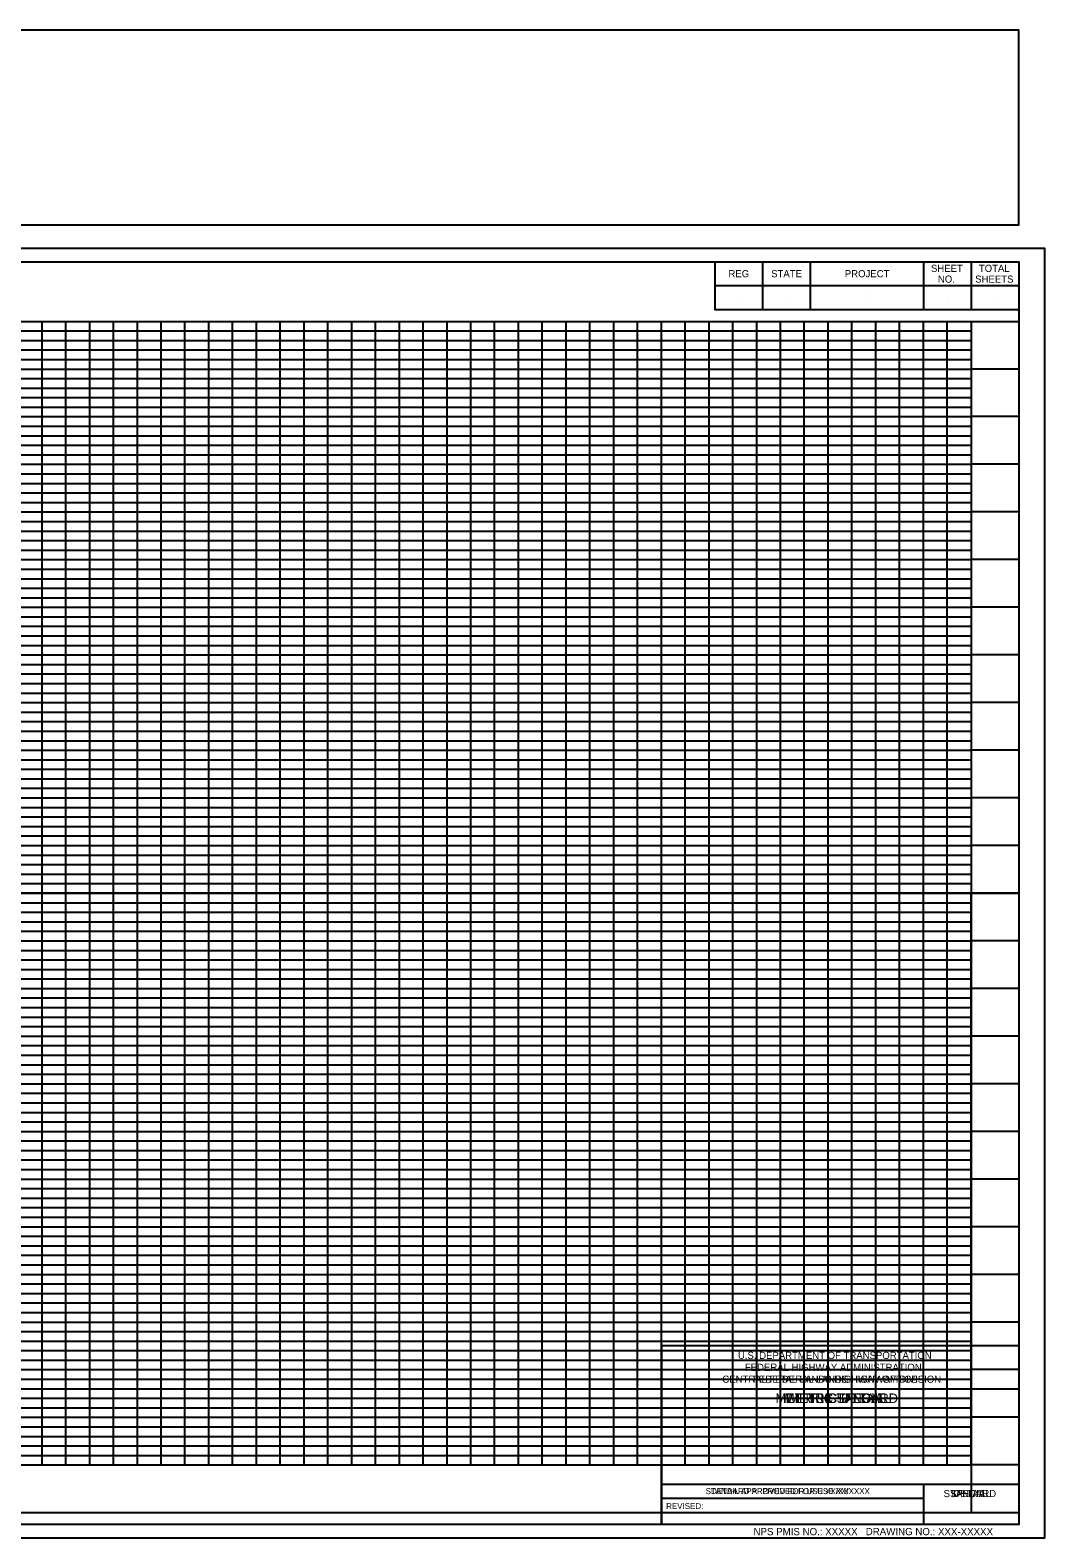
# Model space of a CAD drawing. Extents: x -27 to 395, y -3 to 314.
# Drawn here: x 182.5 to 395.5, y -2.8 to 313.6 of the extents above; entities that cross this region are included whole.
import ezdxf

# ---------------------------------------------------------------- set-up
doc = ezdxf.new("R2010")
doc.units = 0
for name, color, linetype in [('D_CFL_Clip_Boundary_1', 7, 'Continuous'), ('D_CFL_Clip_Boundary_2', 7, 'Continuous'), ('D_CFL_Sheet_Border_ PlotShape', 7, 'Continuous'), ('D_CFL_Sheet_Border_Base', 7, 'Continuous'), ('D_CFL_Sheet_Border_Box', 7, 'Continuous'), ('D_CFL_Sheet_Border_Detail', 7, 'Continuous'), ('D_CFL_Sheet_Border_General', 7, 'Continuous'), ('D_CFL_Sheet_Border_NPS_Pkg', 7, 'Continuous'), ('D_CFL_Sheet_Border_Plan_Plan', 7, 'Continuous'), ('D_CFL_Sheet_Border_PnP', 7, 'Continuous'), ('D_CFL_Sheet_Border_Profile', 7, 'Continuous'), ('D_CFL_Sheet_Border_Project_Info', 7, 'Continuous'), ('D_CFL_Sheet_Border_Special', 7, 'Continuous'), ('D_CFL_Sheet_Border_Standard', 7, 'Continuous')]:
    doc.layers.add(name, color=color, linetype=linetype)

msp = doc.modelspace()

# ---------------------------------------------------------------- linework, layer by layer
at = {"layer": 'D_CFL_Clip_Boundary_1'}
msp.add_lwpolyline([(0, 265), (326.25, 265), (326.25, 255), (390, 255), (390, 132.5), (0, 132.5)], close=True, dxfattribs=at)
at = {"layer": 'D_CFL_Clip_Boundary_2'}
msp.add_lwpolyline([(380, 132.5), (10, 132.5), (10, 12.5), (380, 12.5)], close=True, dxfattribs=at)
at = {"layer": 'D_CFL_Sheet_Border_ PlotShape'}
msp.add_line((395.49, 267.8), (395.49, 267.8), dxfattribs=at)
msp.add_lwpolyline([(-27.13, -2.8), (395.49, -2.8), (395.49, 267.8), (-27.13, 267.8)], close=True, dxfattribs=at)
at = {"layer": 'D_CFL_Sheet_Border_Base'}
for p, q in [((336.25, 265), (336.25, 255)), ((346.25, 265), (346.25, 255)), ((370, 265), (370, 255)), ((380, 265), (380, 255)), ((326.25, 260), (390, 260))]:
    msp.add_line(p, q, dxfattribs=at)
for points in [[(79.54, 272.77), (390, 272.77), (390, 313.62), (79.54, 313.62)], [(0, 265), (390, 265), (390, 0), (0, 0)]]:
    msp.add_lwpolyline(points, close=True, dxfattribs=at)
msp.add_lwpolyline([(326.25, 265), (326.25, 255), (390, 255)], dxfattribs=at)
at = {"layer": 'D_CFL_Sheet_Border_Box'}
for p, q in [((315, 0), (315, 28.5)), ((315, 28.5), (390, 28.5)), ((352.5, 17.25), (352.5, 17.25))]:
    msp.add_line(p, q, dxfattribs=at)
at = {"layer": 'D_CFL_Sheet_Border_Detail'}
for p, q in [((315, 28.5), (390, 28.5)), ((352.5, 17.25), (352.5, 17.25)), ((315, 8.5), (390, 8.5)), ((370, 8.5), (370, 0)), ((315, 5.5), (370, 5.5))]:
    msp.add_line(p, q, dxfattribs=at)
msp.add_lwpolyline([(390, 37.5), (315, 37.5), (315, 0)], dxfattribs=at)
at = {"layer": 'D_CFL_Sheet_Border_General'}
for p, q in [((315, 28.5), (390, 28.5)), ((352.5, 17.25), (352.5, 17.25))]:
    msp.add_line(p, q, dxfattribs=at)
msp.add_lwpolyline([(390, 37.5), (315, 37.5), (315, 0)], dxfattribs=at)
at = {"layer": 'D_CFL_Sheet_Border_Plan_Plan'}
for p, q in [((0, 132.5), (390, 132.5)), ((315, 0), (315, 28.5)), ((315, 28.5), (390, 28.5)), ((352.5, 17.25), (352.5, 17.25))]:
    msp.add_line(p, q, dxfattribs=at)
at = {"layer": 'D_CFL_Sheet_Border_PnP'}
for p, q in [((0, 132.5), (390, 132.5)), ((10, 130.5), (380, 130.5)), ((185, 12.5), (185, 132.5)), ((190, 12.5), (190, 132.5)), ((195, 12.5), (195, 132.5)), ((200, 12.5), (200, 132.5)), ((205, 12.5), (205, 132.5)), ((210, 12.5), (210, 132.5)), ((215, 12.5), (215, 132.5)), ((220, 12.5), (220, 132.5)), ((225, 12.5), (225, 132.5)), ((230, 12.5), (230, 132.5)), ((235, 12.5), (235, 132.5)), ((240, 12.5), (240, 132.5)), ((245, 12.5), (245, 132.5)), ((250, 12.5), (250, 132.5)), ((255, 12.5), (255, 132.5)), ((260, 12.5), (260, 132.5)), ((265, 12.5), (265, 132.5)), ((270, 12.5), (270, 132.5)), ((275, 12.5), (275, 132.5)), ((280, 12.5), (280, 132.5)), ((285, 12.5), (285, 132.5)), ((290, 12.5), (290, 132.5)), ((295, 12.5), (295, 132.5)), ((300, 12.5), (300, 132.5)), ((305, 12.5), (305, 132.5)), ((310, 12.5), (310, 132.5)), ((315, 12.5), (315, 132.5)), ((320, 12.5), (320, 132.5)), ((325, 12.5), (325, 132.5)), ((330, 12.5), (330, 132.5)), ((335, 12.5), (335, 132.5)), ((340, 12.5), (340, 132.5)), ((345, 12.5), (345, 132.5)), ((350, 12.5), (350, 132.5)), ((355, 12.5), (355, 132.5)), ((360, 12.5), (360, 132.5)), ((365, 12.5), (365, 132.5)), ((370, 12.5), (370, 132.5)), ((375, 12.5), (375, 132.5)), ((380, 132.5), (380, 2.5)), ((10, 128.5), (380, 128.5)), ((10, 126.5), (380, 126.5)), ((10, 124.5), (380, 124.5)), ((10, 122.5), (380, 122.5)), ((10, 120.5), (380, 120.5)), ((390, 122.5), (380, 122.5)), ((10, 118.5), (380, 118.5)), ((10, 116.5), (380, 116.5)), ((10, 114.5), (380, 114.5)), ((10, 112.5), (380, 112.5)), ((390, 112.5), (380, 112.5)), ((10, 110.5), (380, 110.5)), ((10, 108.5), (380, 108.5)), ((10, 106.5), (380, 106.5)), ((10, 104.5), (380, 104.5)), ((10, 102.5), (380, 102.5)), ((390, 102.5), (380, 102.5)), ((10, 100.5), (380, 100.5)), ((10, 98.5), (380, 98.5)), ((10, 96.5), (380, 96.5)), ((10, 94.5), (380, 94.5)), ((10, 92.5), (380, 92.5)), ((390, 92.5), (380, 92.5)), ((10, 90.5), (380, 90.5)), ((10, 88.5), (380, 88.5)), ((10, 86.5), (380, 86.5)), ((10, 84.5), (380, 84.5)), ((10, 82.5), (380, 82.5)), ((390, 82.5), (380, 82.5)), ((10, 80.5), (380, 80.5)), ((10, 78.5), (380, 78.5)), ((10, 76.5), (380, 76.5)), ((10, 74.5), (380, 74.5)), ((10, 72.5), (380, 72.5)), ((10, 70.5), (380, 70.5)), ((390, 72.5), (380, 72.5)), ((10, 68.5), (380, 68.5)), ((10, 66.5), (380, 66.5)), ((10, 64.5), (380, 64.5)), ((10, 62.5), (380, 62.5)), ((10, 60.5), (380, 60.5)), ((390, 62.5), (380, 62.5)), ((10, 58.5), (380, 58.5)), ((10, 56.5), (380, 56.5)), ((10, 54.5), (380, 54.5)), ((10, 52.5), (380, 52.5)), ((390, 52.5), (380, 52.5)), ((10, 50.5), (380, 50.5)), ((10, 48.5), (380, 48.5)), ((10, 46.5), (380, 46.5)), ((10, 44.5), (380, 44.5)), ((10, 42.5), (380, 42.5)), ((390, 42.5), (380, 42.5)), ((10, 40.5), (380, 40.5)), ((10, 38.5), (380, 38.5)), ((10, 36.5), (380, 36.5)), ((10, 34.5), (380, 34.5)), ((10, 32.5), (380, 32.5)), ((390, 32.5), (380, 32.5)), ((10, 30.5), (380, 30.5)), ((10, 28.5), (380, 28.5)), ((10, 26.5), (380, 26.5)), ((10, 24.5), (380, 24.5)), ((10, 22.5), (380, 22.5)), ((390, 22.5), (380, 22.5)), ((10, 20.5), (380, 20.5)), ((10, 18.5), (380, 18.5)), ((10, 16.5), (380, 16.5)), ((10, 14.5), (380, 14.5)), ((10, 12.5), (380, 12.5)), ((390, 12.5), (380, 12.5)), ((0, 2.5), (390, 2.5))]:
    msp.add_line(p, q, dxfattribs=at)
at = {"layer": 'D_CFL_Sheet_Border_Profile'}
for p, q in [((0, 252.5), (390, 252.5)), ((10, 250.5), (380, 250.5)), ((185, 12.5), (185, 252.5)), ((190, 12.5), (190, 252.5)), ((195, 12.5), (195, 252.5)), ((200, 12.5), (200, 252.5)), ((205, 12.5), (205, 252.5)), ((210, 12.5), (210, 252.5)), ((215, 12.5), (215, 252.5)), ((220, 12.5), (220, 252.5)), ((225, 12.5), (225, 252.5)), ((230, 12.5), (230, 252.5)), ((235, 12.5), (235, 252.5)), ((240, 12.5), (240, 252.5)), ((245, 12.5), (245, 252.5)), ((250, 12.5), (250, 252.5)), ((255, 12.5), (255, 252.5)), ((260, 12.5), (260, 252.5)), ((265, 12.5), (265, 252.5)), ((270, 12.5), (270, 252.5)), ((275, 12.5), (275, 252.5)), ((280, 12.5), (280, 252.5)), ((285, 12.5), (285, 252.5)), ((290, 12.5), (290, 252.5)), ((295, 12.5), (295, 252.5)), ((300, 12.5), (300, 252.5)), ((305, 12.5), (305, 252.5)), ((310, 12.5), (310, 252.5)), ((315, 12.5), (315, 252.5)), ((320, 12.5), (320, 252.5)), ((325, 12.5), (325, 252.5)), ((330, 12.5), (330, 252.5)), ((335, 12.5), (335, 252.5)), ((340, 12.5), (340, 252.5)), ((345, 12.5), (345, 252.5)), ((350, 12.5), (350, 252.5)), ((355, 12.5), (355, 252.5)), ((360, 12.5), (360, 252.5)), ((365, 12.5), (365, 252.5)), ((370, 12.5), (370, 252.5)), ((375, 12.5), (375, 252.5)), ((380, 252.5), (380, 2.5)), ((10, 248.5), (380, 248.5)), ((10, 246.5), (380, 246.5)), ((10, 244.5), (380, 244.5)), ((10, 242.5), (380, 242.5)), ((10, 240.5), (380, 240.5)), ((390, 242.5), (380, 242.5)), ((10, 238.5), (380, 238.5)), ((10, 236.5), (380, 236.5)), ((10, 234.5), (380, 234.5)), ((10, 232.5), (380, 232.5)), ((390, 232.5), (380, 232.5)), ((10, 230.5), (380, 230.5)), ((10, 228.5), (380, 228.5)), ((10, 226.5), (380, 226.5)), ((10, 224.5), (380, 224.5)), ((10, 222.5), (380, 222.5)), ((390, 222.5), (380, 222.5)), ((10, 220.5), (380, 220.5)), ((10, 218.5), (380, 218.5)), ((10, 216.5), (380, 216.5)), ((10, 214.5), (380, 214.5)), ((10, 212.5), (380, 212.5)), ((390, 212.5), (380, 212.5)), ((10, 210.5), (380, 210.5)), ((10, 208.5), (380, 208.5)), ((10, 206.5), (380, 206.5)), ((10, 204.5), (380, 204.5)), ((10, 202.5), (380, 202.5)), ((10, 200.5), (380, 200.5)), ((390, 202.5), (380, 202.5)), ((10, 198.5), (380, 198.5)), ((10, 196.5), (380, 196.5)), ((10, 194.5), (380, 194.5)), ((10, 192.5), (380, 192.5)), ((10, 190.5), (380, 190.5)), ((390, 192.5), (380, 192.5)), ((10, 188.5), (380, 188.5)), ((10, 186.5), (380, 186.5)), ((10, 184.5), (380, 184.5)), ((10, 182.5), (380, 182.5)), ((10, 180.5), (380, 180.5)), ((390, 182.5), (380, 182.5)), ((10, 178.5), (380, 178.5)), ((10, 176.5), (380, 176.5)), ((10, 174.5), (380, 174.5)), ((10, 172.5), (380, 172.5)), ((390, 172.5), (380, 172.5)), ((10, 170.5), (380, 170.5)), ((10, 168.5), (380, 168.5)), ((10, 166.5), (380, 166.5)), ((10, 164.5), (380, 164.5)), ((10, 162.5), (380, 162.5)), ((390, 162.5), (380, 162.5)), ((10, 160.5), (380, 160.5)), ((10, 158.5), (380, 158.5)), ((10, 156.5), (380, 156.5)), ((10, 154.5), (380, 154.5)), ((10, 152.5), (380, 152.5)), ((390, 152.5), (380, 152.5)), ((10, 150.5), (380, 150.5)), ((10, 148.5), (380, 148.5)), ((10, 146.5), (380, 146.5)), ((10, 144.5), (380, 144.5)), ((10, 142.5), (380, 142.5)), ((390, 142.5), (380, 142.5)), ((10, 140.5), (380, 140.5)), ((10, 138.5), (380, 138.5)), ((10, 136.5), (380, 136.5)), ((10, 134.5), (380, 134.5)), ((10, 132.5), (380, 132.5)), ((10, 130.5), (380, 130.5)), ((390, 132.5), (380, 132.5)), ((10, 128.5), (380, 128.5)), ((10, 126.5), (380, 126.5)), ((10, 124.5), (380, 124.5)), ((10, 122.5), (380, 122.5)), ((10, 120.5), (380, 120.5)), ((390, 122.5), (380, 122.5)), ((10, 118.5), (380, 118.5)), ((10, 116.5), (380, 116.5)), ((10, 114.5), (380, 114.5)), ((10, 112.5), (380, 112.5)), ((390, 112.5), (380, 112.5)), ((10, 110.5), (380, 110.5)), ((10, 108.5), (380, 108.5)), ((10, 106.5), (380, 106.5)), ((10, 104.5), (380, 104.5)), ((10, 102.5), (380, 102.5)), ((390, 102.5), (380, 102.5)), ((10, 100.5), (380, 100.5)), ((10, 98.5), (380, 98.5)), ((10, 96.5), (380, 96.5)), ((10, 94.5), (380, 94.5)), ((10, 92.5), (380, 92.5)), ((390, 92.5), (380, 92.5)), ((10, 90.5), (380, 90.5)), ((10, 88.5), (380, 88.5)), ((10, 86.5), (380, 86.5)), ((10, 84.5), (380, 84.5)), ((10, 82.5), (380, 82.5)), ((390, 82.5), (380, 82.5)), ((10, 80.5), (380, 80.5)), ((10, 78.5), (380, 78.5)), ((10, 76.5), (380, 76.5)), ((10, 74.5), (380, 74.5)), ((10, 72.5), (380, 72.5)), ((10, 70.5), (380, 70.5)), ((390, 72.5), (380, 72.5)), ((10, 68.5), (380, 68.5)), ((10, 66.5), (380, 66.5)), ((10, 64.5), (380, 64.5)), ((10, 62.5), (380, 62.5)), ((10, 60.5), (380, 60.5)), ((390, 62.5), (380, 62.5)), ((10, 58.5), (380, 58.5)), ((10, 56.5), (380, 56.5)), ((10, 54.5), (380, 54.5)), ((10, 52.5), (380, 52.5)), ((390, 52.5), (380, 52.5)), ((10, 50.5), (380, 50.5)), ((10, 48.5), (380, 48.5)), ((10, 46.5), (380, 46.5)), ((10, 44.5), (380, 44.5)), ((10, 42.5), (380, 42.5)), ((390, 42.5), (380, 42.5)), ((10, 40.5), (380, 40.5)), ((10, 38.5), (380, 38.5)), ((10, 36.5), (380, 36.5)), ((10, 34.5), (380, 34.5)), ((10, 32.5), (380, 32.5)), ((390, 32.5), (380, 32.5)), ((10, 30.5), (380, 30.5)), ((10, 28.5), (380, 28.5)), ((10, 26.5), (380, 26.5)), ((10, 24.5), (380, 24.5)), ((10, 22.5), (380, 22.5)), ((390, 22.5), (380, 22.5)), ((10, 20.5), (380, 20.5)), ((10, 18.5), (380, 18.5)), ((10, 16.5), (380, 16.5)), ((10, 14.5), (380, 14.5)), ((10, 12.5), (380, 12.5)), ((390, 12.5), (380, 12.5)), ((0, 2.5), (390, 2.5))]:
    msp.add_line(p, q, dxfattribs=at)
at = {"layer": 'D_CFL_Sheet_Border_Project_Info'}
for p, q in [((331.25, 257.5), (331.25, 257.5)), ((341.25, 257.5), (341.25, 257.5)), ((358.13, 258.68), (358.13, 258.68)), ((358.13, 256.43), (358.13, 256.43)), ((375, 257.5), (375, 257.5)), ((385, 257.5), (385, 257.5))]:
    msp.add_line(p, q, dxfattribs=at)
at = {"layer": 'D_CFL_Sheet_Border_Special'}
for p, q in [((315, 28.5), (390, 28.5)), ((352.5, 17.25), (352.5, 17.25)), ((315, 8.5), (390, 8.5)), ((370, 8.5), (370, 0)), ((315, 5.5), (370, 5.5))]:
    msp.add_line(p, q, dxfattribs=at)
msp.add_lwpolyline([(390, 37.5), (315, 37.5), (315, 0)], dxfattribs=at)
at = {"layer": 'D_CFL_Sheet_Border_Standard'}
for p, q in [((315, 28.5), (390, 28.5)), ((352.5, 17.25), (352.5, 17.25)), ((315, 8.5), (390, 8.5)), ((370, 8.5), (370, 0)), ((315, 5.5), (370, 5.5)), ((380, 3), (380, 3))]:
    msp.add_line(p, q, dxfattribs=at)
msp.add_lwpolyline([(390, 37.5), (315, 37.5), (315, 0)], dxfattribs=at)

# ---------------------------------------------------------------- texts
at = {"layer": 'D_CFL_Sheet_Border_Base'}
for s, p in [('REG', (329.08, 261.75)), ('STATE', (338.04, 261.75)), ('PROJECT', (353.5, 261.75)), ('SHEET', (371.58, 262.88)), ('TOTAL', (381.64, 262.88)), ('NO.', (373.04, 260.62)), ('SHEETS', (380.87, 260.62))]:
    msp.add_text(s, height=1.5, dxfattribs=at).set_placement(p)
at = {"layer": 'D_CFL_Sheet_Border_Detail'}
for s, height, p in [('U.S. DEPARTMENT OF TRANSPORTATION', 1.5, (331.06, 34.75)), ('FEDERAL HIGHWAY ADMINISTRATION', 1.5, (332.52, 32.25)), ('CENTRAL FEDERAL LANDS HIGHWAY DIVISION', 1.5, (327.8, 29.75)), ('METRIC DETAIL', 2, (341.66, 25.5)), ('DETAIL APPROVED FOR USE XX/XXXX', 1.25, (325.41, 6.38)), ('DETAIL', 1.5, (376.26, 5.75)), ('REVISED:                                                 ', 1.25, (316, 3.25))]:
    msp.add_text(s, height=height, dxfattribs=at).set_placement(p)
at = {"layer": 'D_CFL_Sheet_Border_General'}
for s, p in [('U.S. DEPARTMENT OF TRANSPORTATION', (331.06, 34.75)), ('FEDERAL HIGHWAY ADMINISTRATION', (332.52, 32.25)), ('CENTRAL FEDERAL LANDS HIGHWAY DIVISION', (327.8, 29.75))]:
    msp.add_text(s, height=1.5, dxfattribs=at).set_placement(p)
at = {"layer": 'D_CFL_Sheet_Border_NPS_Pkg'}
msp.add_text('NPS PMIS NO.: XXXXX   DRAWING NO.: XXX-XXXXX', height=1.524, dxfattribs=at).set_placement((334.33, -2.25))
at = {"layer": 'D_CFL_Sheet_Border_Special'}
for s, height, p in [('U.S. DEPARTMENT OF TRANSPORTATION', 1.5, (331.06, 34.75)), ('FEDERAL HIGHWAY ADMINISTRATION', 1.5, (332.52, 32.25)), ('CENTRAL FEDERAL LANDS HIGHWAY DIVISION', 1.5, (327.8, 29.75)), ('METRIC SPECIAL', 2, (340.76, 25.5)), ('SPECIAL', 1.5, (375.59, 5.75))]:
    msp.add_text(s, height=height, dxfattribs=at).set_placement(p)
at = {"layer": 'D_CFL_Sheet_Border_Standard'}
for s, height, p in [('U.S. DEPARTMENT OF TRANSPORTATION', 1.5, (331.06, 34.75)), ('FEDERAL HIGHWAY ADMINISTRATION', 1.5, (332.52, 32.25)), ('FEDERAL LANDS HIGHWAY OFFICE', 1.5, (334.22, 29.75)), ('METRIC STANDARD', 2, (338.95, 25.5)), ('STANDARD APPROVED FOR USE XX/XXXX', 1.25, (324.29, 6.38)), ('STANDARD', 1.5, (374.23, 5.75)), ('REVISED:                                                 ', 1.25, (316, 3.25))]:
    msp.add_text(s, height=height, dxfattribs=at).set_placement(p)

doc.saveas('drawing.dxf')
